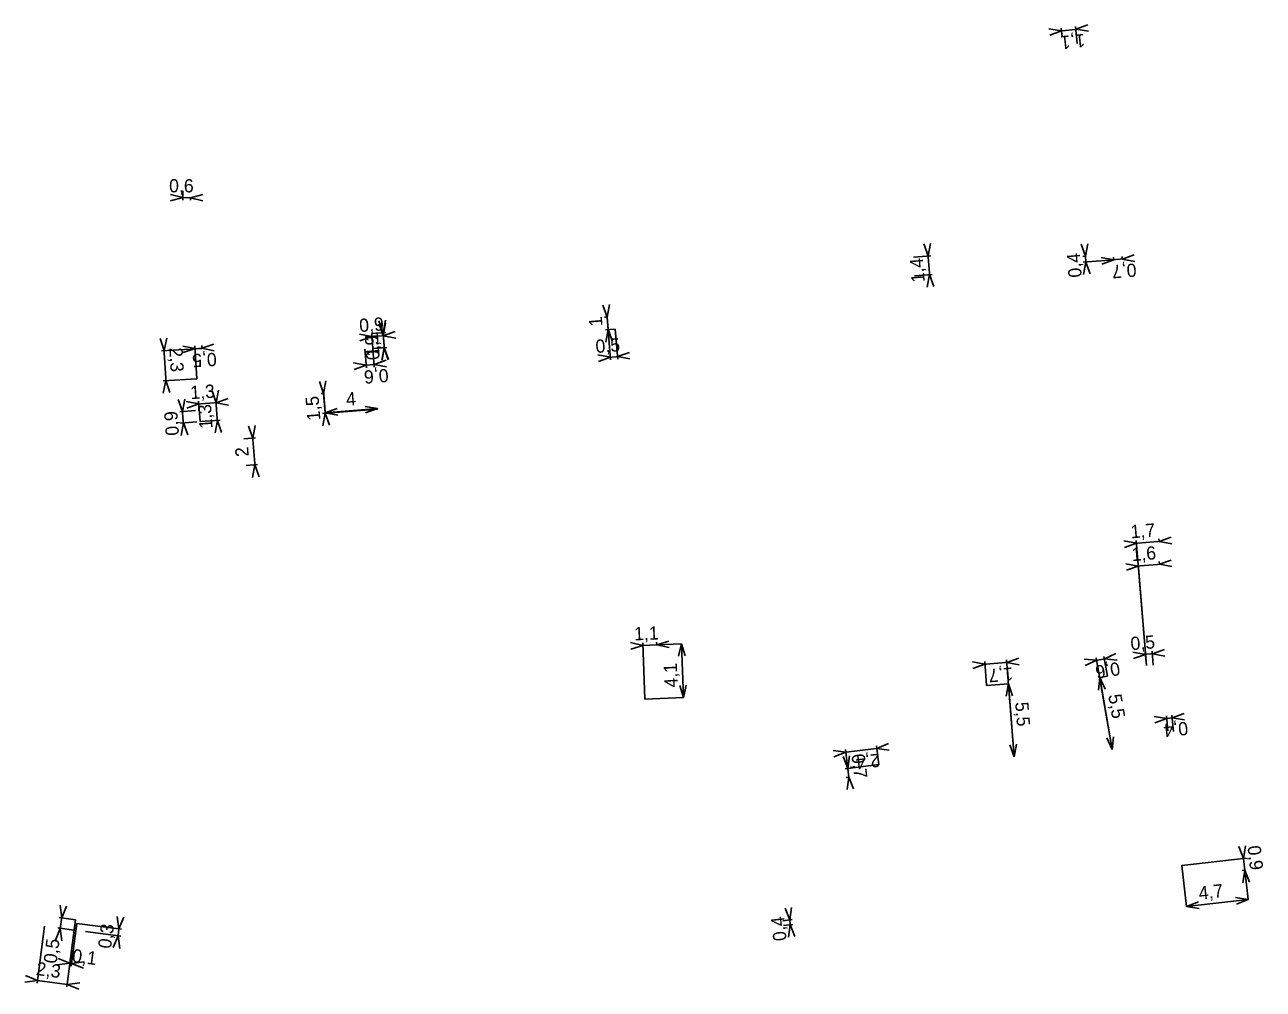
# Model space of a CAD drawing. Extents: x -744711.7 to -744618, y -1052409.1 to -1052336.2.
import ezdxf

# ---------------------------------------------------------------- set-up
doc = ezdxf.new("R2010")
doc.units = 0
doc.layers.add('Kota_NN', color=7, linetype='Continuous')

msp = doc.modelspace()

# ---------------------------------------------------------------- linework, layer by layer
at = {"layer": 'Kota_NN'}
for p, q in [((-744633.191, -1052337.09), (-744633.259, -1052336.427)), ((-744632.05, -1052337.58), (-744632.179, -1052336.317)), ((-744632.159, -1052336.516), (-744631.261, -1052336.175)), ((-744633.238, -1052336.626), (-744634.187, -1052336.473)), ((-744633.238, -1052336.626), (-744634.136, -1052336.967)), ((-744631.96, -1052336.495), (-744633.437, -1052336.646)), ((-744632.159, -1052336.516), (-744631.21, -1052336.669)), ((-744699.711, -1052349.251), (-744700.639, -1052349)), ((-744699.711, -1052349.251), (-744700.639, -1052349.497)), ((-744699.911, -1052349.251), (-744698.94, -1052349.252)), ((-744699.71, -1052348.735), (-744699.711, -1052349.451)), ((-744699.14, -1052349.252), (-744698.212, -1052349.006)), ((-744699.14, -1052349.25), (-744699.14, -1052349.452)), ((-744699.14, -1052349.252), (-744698.212, -1052349.503)), ((-744643.337, -1052353.659), (-744643.658, -1052352.754)), ((-744643.337, -1052353.659), (-744643.163, -1052352.714)), ((-744631.43, -1052353.68), (-744631.751, -1052352.775)), ((-744631.43, -1052353.68), (-744631.256, -1052352.735)), ((-744644.447, -1052353.748), (-744643.138, -1052353.643)), ((-744643.208, -1052355.268), (-744643.353, -1052353.46)), ((-744631.43, -1052353.68), (-744631.629, -1052353.696)), ((-744629.29, -1052353.95), (-744631.594, -1052354.135)), ((-744631.395, -1052354.119), (-744631.569, -1052355.064)), ((-744631.379, -1052354.318), (-744631.446, -1052353.481)), ((-744631.395, -1052354.119), (-744631.074, -1052355.024)), ((-744629.29, -1052353.949), (-744630.235, -1052353.775)), ((-744629.29, -1052353.949), (-744630.195, -1052354.271)), ((-744628.443, -1052353.88), (-744629.489, -1052353.965)), ((-744629.29, -1052353.95), (-744629.306, -1052353.749)), ((-744628.64, -1052353.92), (-744628.658, -1052353.697)), ((-744628.642, -1052353.897), (-744627.737, -1052353.575)), ((-744628.642, -1052353.897), (-744627.697, -1052354.071)), ((-744644.36, -1052355.16), (-744643.025, -1052355.053)), ((-744643.224, -1052355.069), (-744643.398, -1052356.014)), ((-744643.224, -1052355.069), (-744642.903, -1052355.974)), ((-744667.61, -1052358.28), (-744667.931, -1052357.375)), ((-744667.61, -1052358.28), (-744667.436, -1052357.335)), ((-744684.56, -1052359.465), (-744684.881, -1052358.56)), ((-744684.55, -1052359.69), (-744684.866, -1052358.783)), ((-744684.56, -1052359.465), (-744684.386, -1052358.52)), ((-744684.55, -1052359.69), (-744684.37, -1052358.746)), ((-744667.61, -1052358.28), (-744667.809, -1052358.296)), ((-744667.518, -1052359.432), (-744667.626, -1052358.081)), ((-744667.61, -1052358.28), (-744667.35, -1052361.518)), ((-744701.127, -1052360.814), (-744700.932, -1052359.873)), ((-744685.407, -1052359.753), (-744686.351, -1052359.573)), ((-744685.407, -1052359.753), (-744686.314, -1052360.069)), ((-744685.607, -1052359.768), (-744684.351, -1052359.675)), ((-744685.433, -1052359.535), (-744684.361, -1052359.449)), ((-744685.34, -1052360.66), (-744685.422, -1052359.554)), ((-744684.454, -1052360.79), (-744684.576, -1052359.266)), ((-744684.55, -1052359.69), (-744684.565, -1052359.49)), ((-744684.468, -1052360.796), (-744684.565, -1052359.491)), ((-744684.55, -1052359.69), (-744683.643, -1052359.374)), ((-744684.55, -1052359.69), (-744684.351, -1052359.675)), ((-744684.55, -1052359.69), (-744683.606, -1052359.87)), ((-744667, -1052359.19), (-744667.733, -1052359.249)), ((-744667.534, -1052359.233), (-744667.708, -1052360.178)), ((-744667.534, -1052359.233), (-744667.213, -1052360.138)), ((-744667, -1052359.19), (-744666.817, -1052361.476)), ((-744701.127, -1052360.814), (-744701.428, -1052359.902)), ((-744698.27, -1052360.65), (-744701.327, -1052360.826)), ((-744701.138, -1052360.615), (-744700.985, -1052363.285)), ((-744698.784, -1052360.668), (-744699.725, -1052360.474)), ((-744698.784, -1052360.668), (-744699.696, -1052360.97)), ((-744698.071, -1052360.626), (-744698.984, -1052360.68)), ((-744698.65, -1052362.95), (-744698.796, -1052360.469)), ((-744698.27, -1052360.65), (-744698.282, -1052360.439)), ((-744698.271, -1052360.638), (-744697.359, -1052360.336)), ((-744698.271, -1052360.638), (-744697.33, -1052360.832)), ((-744685.94, -1052360.711), (-744685.83, -1052362.116)), ((-744685.34, -1052360.66), (-744684.271, -1052360.574)), ((-744685.34, -1052360.66), (-744684.283, -1052360.582)), ((-744685.34, -1052360.66), (-744685.229, -1052362.069)), ((-744684.483, -1052360.597), (-744684.663, -1052361.541)), ((-744684.47, -1052360.59), (-744684.644, -1052361.535)), ((-744684.483, -1052360.597), (-744684.167, -1052361.504)), ((-744684.47, -1052360.59), (-744684.149, -1052361.495)), ((-744685.845, -1052361.916), (-744686.79, -1052361.74)), ((-744685.245, -1052361.869), (-744684.339, -1052361.549)), ((-744667.366, -1052361.319), (-744668.311, -1052361.145)), ((-744667.366, -1052361.319), (-744668.271, -1052361.64)), ((-744667.566, -1052361.335), (-744666.633, -1052361.26)), ((-744666.833, -1052361.276), (-744665.928, -1052360.955)), ((-744666.833, -1052361.276), (-744665.888, -1052361.45)), ((-744685.845, -1052361.916), (-744686.751, -1052362.236)), ((-744685.046, -1052361.854), (-744686.045, -1052361.932)), ((-744685.245, -1052361.869), (-744684.3, -1052362.045)), ((-744698.65, -1052362.95), (-744701.196, -1052363.096)), ((-744700.996, -1052363.085), (-744701.191, -1052364.026)), ((-744700.996, -1052363.085), (-744700.695, -1052363.997)), ((-744689.06, -1052364.05), (-744689.382, -1052363.145)), ((-744689.06, -1052364.05), (-744688.887, -1052363.105)), ((-744699.737, -1052365.424), (-744700.058, -1052364.519)), ((-744699.737, -1052365.424), (-744699.563, -1052364.479)), ((-744697.19, -1052364.76), (-744697.503, -1052363.852)), ((-744697.19, -1052364.76), (-744697.204, -1052364.56)), ((-744697.081, -1052366.297), (-744697.204, -1052364.56)), ((-744697.19, -1052364.76), (-744697.007, -1052363.817)), ((-744697.19, -1052364.76), (-744696.282, -1052364.447)), ((-744689.06, -1052364.05), (-744689.259, -1052364.066)), ((-744688.921, -1052365.761), (-744689.076, -1052363.851)), ((-744689.06, -1052364.05), (-744688.94, -1052365.528)), ((-744698.746, -1052365.344), (-744699.936, -1052365.44)), ((-744699.652, -1052366.49), (-744699.753, -1052365.224)), ((-744698.505, -1052364.853), (-744699.448, -1052364.67)), ((-744698.505, -1052364.853), (-744699.413, -1052365.166)), ((-744698.704, -1052364.867), (-744696.99, -1052364.746)), ((-744698.41, -1052366.19), (-744698.519, -1052364.653)), ((-744697.19, -1052364.76), (-744696.99, -1052364.746)), ((-744697.19, -1052364.76), (-744696.247, -1052364.943)), ((-744684.98, -1052365.24), (-744689.137, -1052365.577)), ((-744688.94, -1052365.528), (-744688.035, -1052365.206)), ((-744688.94, -1052365.528), (-744684.983, -1052365.207)), ((-744684.983, -1052365.207), (-744685.928, -1052365.034)), ((-744684.983, -1052365.207), (-744685.888, -1052365.529)), ((-744684.98, -1052365.24), (-744684.983, -1052365.207)), ((-744698.661, -1052366.21), (-744699.867, -1052366.307)), ((-744699.668, -1052366.291), (-744699.842, -1052367.236)), ((-744699.668, -1052366.291), (-744699.347, -1052367.196)), ((-744698.41, -1052366.19), (-744696.896, -1052366.083)), ((-744697.095, -1052366.097), (-744697.278, -1052367.04)), ((-744697.095, -1052366.097), (-744696.782, -1052367.005)), ((-744688.937, -1052365.561), (-744689.11, -1052366.506)), ((-744688.94, -1052365.528), (-744687.995, -1052365.701)), ((-744688.937, -1052365.561), (-744688.615, -1052366.466)), ((-744694.425, -1052367.435), (-744694.746, -1052366.53)), ((-744694.247, -1052369.657), (-744694.441, -1052367.235)), ((-744694.425, -1052367.435), (-744694.251, -1052366.49)), ((-744695.11, -1052367.49), (-744694.226, -1052367.419)), ((-744694.934, -1052369.511), (-744694.063, -1052369.442)), ((-744694.263, -1052369.458), (-744694.437, -1052370.403)), ((-744694.263, -1052369.458), (-744693.942, -1052370.363)), ((-744627.57, -1052375.389), (-744628.515, -1052375.216)), ((-744627.57, -1052375.389), (-744628.475, -1052375.711)), ((-744627.769, -1052375.406), (-744625.651, -1052375.234)), ((-744626.82, -1052384.64), (-744627.586, -1052375.19)), ((-744625.85, -1052375.25), (-744625.866, -1052375.051)), ((-744625.85, -1052375.25), (-744624.945, -1052374.928)), ((-744625.85, -1052375.25), (-744624.905, -1052375.423)), ((-744625.84, -1052376.98), (-744624.935, -1052376.658)), ((-744627.43, -1052377.109), (-744628.375, -1052376.936)), ((-744627.43, -1052377.109), (-744628.335, -1052377.431)), ((-744627.63, -1052377.125), (-744625.641, -1052376.964)), ((-744626.82, -1052384.64), (-744627.447, -1052376.91)), ((-744625.84, -1052376.98), (-744625.856, -1052376.781)), ((-744625.84, -1052376.98), (-744624.895, -1052377.153)), ((-744664.913, -1052383.112), (-744665.85, -1052382.9)), ((-744664.913, -1052383.112), (-744665.83, -1052383.397)), ((-744665.113, -1052383.12), (-744663.66, -1052383.062)), ((-744664.75, -1052387.18), (-744664.921, -1052382.912)), ((-744663.86, -1052383.07), (-744663.868, -1052382.87)), ((-744663.86, -1052383.07), (-744662.943, -1052382.785)), ((-744663.86, -1052383.07), (-744661.999, -1052382.996)), ((-744663.86, -1052383.07), (-744662.923, -1052383.282)), ((-744661.999, -1052382.996), (-744662.211, -1052383.933)), ((-744661.836, -1052387.063), (-744661.999, -1052382.996)), ((-744661.999, -1052382.996), (-744661.714, -1052383.913)), ((-744636.83, -1052391.53), (-744637.399, -1052384.206)), ((-744637.383, -1052384.406), (-744636.477, -1052384.087)), ((-744630.577, -1052384.239), (-744631.534, -1052384.153)), ((-744629.8, -1052384.104), (-744630.774, -1052384.273)), ((-744629.4, -1052390.98), (-744630.611, -1052384.042)), ((-744629.77, -1052385.44), (-744630.032, -1052383.941)), ((-744629.997, -1052384.138), (-744629.125, -1052383.734)), ((-744629.997, -1052384.138), (-744629.04, -1052384.224)), ((-744626.889, -1052383.795), (-744627.834, -1052383.622)), ((-744626.889, -1052383.795), (-744627.794, -1052384.117)), ((-744627.088, -1052383.811), (-744626.165, -1052383.736)), ((-744626.82, -1052384.64), (-744626.905, -1052383.595)), ((-744626.296, -1052384.598), (-744626.381, -1052383.553)), ((-744626.365, -1052383.752), (-744625.46, -1052383.43)), ((-744626.365, -1052383.752), (-744625.42, -1052383.925)), ((-744639.036, -1052384.534), (-744639.98, -1052384.358)), ((-744639.036, -1052384.534), (-744639.942, -1052384.853)), ((-744637.184, -1052384.39), (-744639.235, -1052384.55)), ((-744638.91, -1052386.15), (-744639.051, -1052384.335)), ((-744637.383, -1052384.406), (-744636.439, -1052384.582)), ((-744630.577, -1052384.239), (-744631.449, -1052384.643)), ((-744638.91, -1052386.15), (-744637.258, -1052386.022)), ((-744637.258, -1052386.022), (-744637.434, -1052386.966)), ((-744637.258, -1052386.022), (-744636.83, -1052391.53)), ((-744637.258, -1052386.022), (-744636.939, -1052386.928)), ((-744630.349, -1052385.541), (-744630.435, -1052386.498)), ((-744629.77, -1052385.44), (-744630.349, -1052385.541)), ((-744630.349, -1052385.541), (-744629.4, -1052390.98)), ((-744630.349, -1052385.541), (-744629.945, -1052386.413)), ((-744661.836, -1052387.063), (-744662.121, -1052386.146)), ((-744661.836, -1052387.063), (-744661.624, -1052386.126)), ((-744664.75, -1052387.18), (-744661.836, -1052387.063)), ((-744625.283, -1052388.636), (-744626.231, -1052388.481)), ((-744625.283, -1052388.636), (-744626.182, -1052388.976)), ((-744624.674, -1052388.575), (-744625.482, -1052388.656)), ((-744625.188, -1052389.579), (-744625.303, -1052388.437)), ((-744624.769, -1052389.623), (-744624.893, -1052388.396)), ((-744624.873, -1052388.595), (-744623.974, -1052388.255)), ((-744624.873, -1052388.595), (-744623.925, -1052388.75)), ((-744647.07, -1052392.13), (-744647.246, -1052390.705)), ((-744647.221, -1052390.904), (-744646.33, -1052390.544)), ((-744636.83, -1052391.53), (-744637.149, -1052390.624)), ((-744636.83, -1052391.53), (-744636.654, -1052390.586)), ((-744629.4, -1052390.98), (-744629.804, -1052390.108)), ((-744629.4, -1052390.98), (-744629.314, -1052390.023)), ((-744649.561, -1052391.192), (-744650.512, -1052391.058)), ((-744649.561, -1052391.192), (-744650.452, -1052391.552)), ((-744649.41, -1052392.418), (-744649.77, -1052391.527)), ((-744647.023, -1052390.879), (-744649.76, -1052391.217)), ((-744649.33, -1052393.07), (-744649.586, -1052390.994)), ((-744649.41, -1052392.418), (-744649.276, -1052391.467)), ((-744647.221, -1052390.904), (-744646.27, -1052391.038)), ((-744636.83, -1052391.53), (-744636.83, -1052391.53)), ((-744629.4, -1052390.98), (-744629.4, -1052390.98)), ((-744647.07, -1052392.13), (-744649.609, -1052392.443)), ((-744649.435, -1052392.22), (-744649.306, -1052393.269)), ((-744649.33, -1052393.07), (-744649.529, -1052393.094)), ((-744649.33, -1052393.07), (-744649.464, -1052394.021)), ((-744649.33, -1052393.07), (-744648.97, -1052393.961)), ((-744619.473, -1052399.224), (-744619.332, -1052398.274)), ((-744624.13, -1052399.76), (-744619.274, -1052399.201)), ((-744619.473, -1052399.224), (-744619.825, -1052398.33)), ((-744619.496, -1052399.026), (-744619.347, -1052400.319)), ((-744624.13, -1052399.76), (-744623.773, -1052402.865)), ((-744619.37, -1052400.12), (-744619.569, -1052400.143)), ((-744619.37, -1052400.12), (-744619.511, -1052401.07)), ((-744619.37, -1052400.12), (-744619.116, -1052402.329)), ((-744619.37, -1052400.12), (-744619.018, -1052401.014)), ((-744708.877, -1052403.725), (-744709.003, -1052402.773)), ((-744708.877, -1052403.725), (-744708.51, -1052402.837)), ((-744653.805, -1052403.875), (-744653.663, -1052402.925)), ((-744623.773, -1052402.865), (-744619.116, -1052402.329)), ((-744623.773, -1052402.865), (-744622.879, -1052402.513)), ((-744623.773, -1052402.865), (-744622.823, -1052403.006)), ((-744619.116, -1052402.329), (-744620.066, -1052402.188)), ((-744619.116, -1052402.329), (-744620.01, -1052402.681)), ((-744707.83, -1052403.862), (-744709.075, -1052403.699)), ((-744709.006, -1052404.711), (-744708.851, -1052403.527)), ((-744707.83, -1052403.862), (-744708.495, -1052408.949)), ((-744707.83, -1052403.862), (-744708.286, -1052407.348)), ((-744704.544, -1052404.558), (-744704.67, -1052403.606)), ((-744704.544, -1052404.558), (-744704.177, -1052403.67)), ((-744654.312, -1052403.933), (-744653.606, -1052403.853)), ((-744653.805, -1052403.875), (-744654.157, -1052402.981)), ((-744653.741, -1052404.432), (-744653.827, -1052403.677)), ((-744710.18, -1052404.34), (-744710.744, -1052408.656)), ((-744708.98, -1052404.513), (-744709.347, -1052405.401)), ((-744707.778, -1052404.67), (-744709.178, -1052404.487)), ((-744708.98, -1052404.513), (-744708.854, -1052405.465)), ((-744707.73, -1052404.142), (-744708.151, -1052407.366)), ((-744707.73, -1052404.142), (-744704.345, -1052404.584)), ((-744707.087, -1052404.764), (-744704.414, -1052405.113)), ((-744704.639, -1052405.286), (-744704.518, -1052404.36)), ((-744654.26, -1052404.29), (-744653.565, -1052404.211)), ((-744653.764, -1052404.233), (-744653.906, -1052405.183)), ((-744653.764, -1052404.233), (-744653.412, -1052405.127)), ((-744704.613, -1052405.087), (-744704.98, -1052405.975)), ((-744704.613, -1052405.087), (-744704.487, -1052406.039)), ((-744708.26, -1052407.15), (-744709.212, -1052407.276)), ((-744708.26, -1052407.15), (-744709.148, -1052406.783)), ((-744708.458, -1052407.124), (-744707.927, -1052407.193)), ((-744708.125, -1052407.167), (-744707.173, -1052407.041)), ((-744708.125, -1052407.167), (-744707.237, -1052407.534)), ((-744710.718, -1052408.457), (-744711.67, -1052408.583)), ((-744710.718, -1052408.457), (-744711.606, -1052408.09)), ((-744710.916, -1052408.431), (-744708.271, -1052408.777)), ((-744708.469, -1052408.751), (-744707.517, -1052408.625)), ((-744708.469, -1052408.751), (-744707.581, -1052409.118))]:
    msp.add_line(p, q, dxfattribs=at)

# ---------------------------------------------------------------- texts
for s, rotation, p in [('1,1', 185.83837, (-744631.507, -1052336.851)), ('0,6', 359.88897, (-744700.752, -1052348.849)), ('1,4', 94.5903, (-744643.58, -1052355.632)), ('0,4', 94.59048, (-744631.705, -1052355.255)), ('0,7', 184.60132, (-744627.612, -1052354.215)), ('0,9', 4.23331, (-744686.331, -1052359.421)), ('1', 94.58626, (-744667.958, -1052358.953)), ('0,9', 94.22986, (-744684.817, -1052361.496)), ('1,1', 94.58229, (-744684.822, -1052361.214)), ('0,5', 4.58295, (-744668.455, -1052361.005)), ('2,3', 273.29145, (-744700.738, -1052360.602)), ('0,5', 183.37264, (-744697.18, -1052360.975)), ('0,6', 184.49416, (-744684.191, -1052362.188)), ('1,3', 4.04748, (-744699.113, -1052364.495)), ('1,5', 94.64, (-744689.297, -1052366.074)), ('4', 4.63918, (-744687.328, -1052364.995)), ('0,9', 94.57456, (-744699.995, -1052367.212)), ('1,3', 94.04643, (-744697.454, -1052366.694)), ('2', 94.5892, (-744694.716, -1052368.812)), ('1,7', 4.63462, (-744627.978, -1052375.021)), ('1,6', 4.63451, (-744627.904, -1052376.746)), ('1,1', 2.29026, (-744665.559, -1052382.737)), ('0,5', 4.63471, (-744627.981, -1052383.482)), ('4,1', 92.29114, (-744662.267, -1052386.288)), ('1,7', 184.44166, (-744636.942, -1052384.773)), ('0,6', 189.90197, (-744628.911, -1052384.355)), ('5,5', 279.90001, (-744629.709, -1052386.885)), ('5,5', 274.44062, (-744636.748, -1052387.422)), ('0,4', 185.74694, (-744623.718, -1052388.88)), ('0,7', 277.02327, (-744649.135, -1052391.378)), ('2,4', 187.02423, (-744647.025, -1052391.283)), ('0,9', 276.56316, (-744619.176, -1052398.308)), ('4,7', 6.56437, (-744622.808, -1052402.352)), ('0,4', 96.50847, (-744654.032, -1052405.418)), ('0,3', 82.5545, (-744705.147, -1052406.087)), ('0,5', 82.55455, (-744709.269, -1052407.211)), ('0,1', 352.55407, (-744708.132, -1052407.053)), ('2,3', 352.55516, (-744710.858, -1052408.036))]:
    msp.add_text(s, height=1, rotation=rotation, dxfattribs=at).set_placement(p)

doc.saveas('drawing.dxf')
